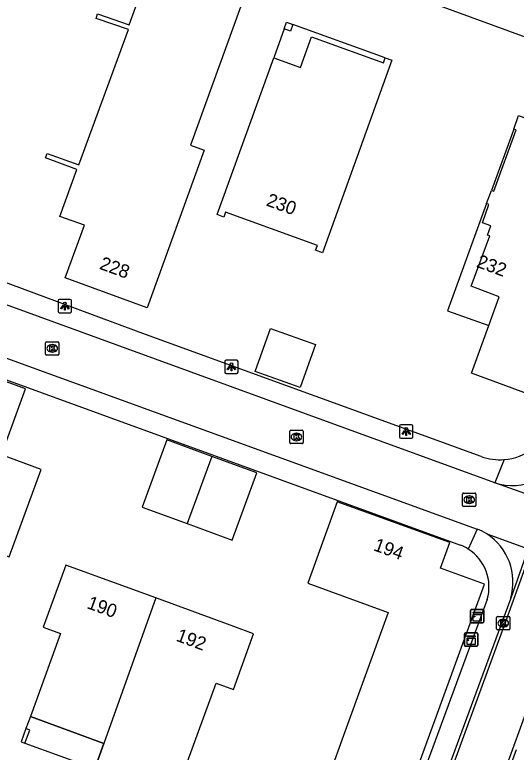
# Model space of a CAD drawing. Extents: x 155275 to 156263, y 382654 to 383635.
# Drawn here: x 155952.1 to 155989.7, y 382926.2 to 382981.5 of the extents above; entities that cross this region are included whole.
import ezdxf

# ---------------------------------------------------------------- set-up
doc = ezdxf.new("R2010")
doc.units = 0
for name, color, linetype in [('IMGEO_Kast', 7, 'Continuous'), ('IMGEO_Kolk', 7, 'Continuous'), ('IMGEO_Lichtpunt', 7, 'Continuous'), ('IMGEO_Pand', 7, 'Continuous'), ('IMGEO_Pand_nummerreeks', 7, 'Continuous'), ('IMGEO_Pand_overbouw', 7, 'Continuous'), ('IMGEO_Rijbaan_lokaal_gesloten', 7, 'Continuous'), ('IMGEO_Rijbaan_lokaal_open', 7, 'Continuous'), ('IMGEO_Voetpad_open', 7, 'Continuous')]:
    doc.layers.add(name, color=color, linetype=linetype)

msp = doc.modelspace()

# ---------------------------------------------------------------- linework, layer by layer
at = {"layer": 'IMGEO_Kast'}
for p, q in [((155986.365, 382936.948), (155987.206, 382936.948)), ((155987.206, 382936.948), (155986.365, 382936.948)), ((155986.29, 382936.023), (155986.29, 382936.864)), ((155986.29, 382936.864), (155986.29, 382936.023)), ((155987.29, 382936.873), (155987.29, 382936.032)), ((155987.29, 382936.032), (155987.29, 382936.873)), ((155987.215, 382935.948), (155986.374, 382935.948)), ((155986.374, 382935.948), (155987.215, 382935.948)), ((155985.83, 382934.257), (155985.83, 382935.098)), ((155985.83, 382935.098), (155985.83, 382934.257)), ((155985.905, 382935.182), (155986.746, 382935.182)), ((155986.746, 382935.182), (155985.905, 382935.182)), ((155986.83, 382935.107), (155986.83, 382934.266)), ((155986.83, 382934.266), (155986.83, 382935.107)), ((155986.755, 382934.182), (155985.914, 382934.182)), ((155985.914, 382934.182), (155986.755, 382934.182))]:
    msp.add_line(p, q, dxfattribs=at)
for points in [[(155986.485, 382936.738), (155987.085, 382936.738), (155987.085, 382936.653), (155986.485, 382936.653), (155986.485, 382936.738)], [(155986.485, 382936.563), (155987.085, 382936.563), (155987.085, 382936.074), (155986.485, 382936.074), (155986.485, 382936.563)], [(155986.025, 382934.972), (155986.625, 382934.972), (155986.625, 382934.887), (155986.025, 382934.887), (155986.025, 382934.972)], [(155986.025, 382934.797), (155986.625, 382934.797), (155986.625, 382934.308), (155986.025, 382934.308), (155986.025, 382934.797)]]:
    msp.add_lwpolyline(points, dxfattribs=at)
for centre in [(155986.569, 382936.412), (155986.109, 382934.646)]:
    msp.add_circle(centre, 0.0377, dxfattribs=at)
for centre, start, end in [((155986.368, 382936.87), 92.4484, 184.2845), ((155986.368, 382936.87), 92.4484, 184.2845), ((155987.212, 382936.87), 2.4484, 94.2845), ((155987.212, 382936.87), 2.4484, 94.2845), ((155986.368, 382936.026), 182.4484, 274.2845), ((155986.368, 382936.026), 182.4484, 274.2845), ((155987.212, 382936.026), 272.4484, 4.2845), ((155987.212, 382936.026), 272.4484, 4.2845), ((155985.908, 382935.104), 92.4484, 184.2845), ((155985.908, 382935.104), 92.4484, 184.2845), ((155986.752, 382935.104), 2.4484, 94.2845), ((155986.752, 382935.104), 2.4484, 94.2845), ((155985.908, 382934.26), 182.4484, 274.2845), ((155985.908, 382934.26), 182.4484, 274.2845), ((155986.752, 382934.26), 272.4484, 4.2845), ((155986.752, 382934.26), 272.4484, 4.2845)]:
    msp.add_arc(centre, 0.0779, start, end, dxfattribs=at)
at = {"layer": 'IMGEO_Kolk'}
for p, q in [((155954.389, 382956.097), (155954.389, 382956.949)), ((155954.464, 382957.023), (155955.316, 382957.023)), ((155954.877, 382956.803), (155954.902, 382956.803)), ((155955.39, 382956.949), (155955.39, 382956.097)), ((155954.9, 382956.243), (155954.875, 382956.243)), ((155955.316, 382956.023), (155954.464, 382956.023)), ((155972.719, 382949.453), (155972.719, 382950.305)), ((155972.794, 382950.379), (155973.646, 382950.379)), ((155973.207, 382950.159), (155973.232, 382950.159)), ((155973.72, 382950.305), (155973.72, 382949.453)), ((155973.646, 382949.379), (155972.794, 382949.379)), ((155973.23, 382949.599), (155973.205, 382949.599)), ((155985.689, 382944.749), (155985.689, 382945.601)), ((155985.764, 382945.675), (155986.616, 382945.675)), ((155986.177, 382945.455), (155986.202, 382945.455)), ((155986.69, 382945.601), (155986.69, 382944.749)), ((155986.616, 382944.675), (155985.764, 382944.675)), ((155986.2, 382944.895), (155986.175, 382944.895)), ((155988.245, 382935.49), (155988.245, 382936.342)), ((155988.32, 382936.416), (155989.172, 382936.416)), ((155989.246, 382936.342), (155989.246, 382935.49)), ((155988.733, 382936.196), (155988.758, 382936.196)), ((155989.172, 382935.416), (155988.32, 382935.416)), ((155988.756, 382935.636), (155988.731, 382935.636))]:
    msp.add_line(p, q, dxfattribs=at)
for points in [[(155954.389, 382956.097), (155954.389, 382956.949)], [(155954.464, 382957.023), (155955.316, 382957.023)], [(155955.39, 382956.949), (155955.39, 382956.097)], [(155954.71, 382956.723), (155954.833, 382956.723), (155954.833, 382956.572), (155954.963, 382956.723), (155955.127, 382956.723), (155954.981, 382956.572), (155955.134, 382956.323), (155954.982, 382956.323), (155954.897, 382956.487), (155954.833, 382956.42), (155954.833, 382956.323), (155954.71, 382956.323), (155954.71, 382956.723)], [(155955.316, 382956.023), (155954.464, 382956.023)], [(155972.719, 382949.453), (155972.719, 382950.305)], [(155972.794, 382950.379), (155973.646, 382950.379)], [(155973.72, 382950.305), (155973.72, 382949.453)], [(155973.04, 382950.079), (155973.163, 382950.079), (155973.163, 382949.928), (155973.293, 382950.079), (155973.457, 382950.079), (155973.311, 382949.928), (155973.464, 382949.679), (155973.312, 382949.679), (155973.227, 382949.843), (155973.163, 382949.776), (155973.163, 382949.679), (155973.04, 382949.679), (155973.04, 382950.079)], [(155973.646, 382949.379), (155972.794, 382949.379)], [(155985.689, 382944.749), (155985.689, 382945.601)], [(155985.764, 382945.675), (155986.616, 382945.675)], [(155986.01, 382945.375), (155986.133, 382945.375), (155986.133, 382945.224), (155986.263, 382945.375), (155986.427, 382945.375), (155986.281, 382945.224), (155986.434, 382944.975), (155986.282, 382944.975), (155986.197, 382945.139), (155986.133, 382945.072), (155986.133, 382944.975), (155986.01, 382944.975), (155986.01, 382945.375)], [(155986.69, 382945.601), (155986.69, 382944.749)], [(155986.616, 382944.675), (155985.764, 382944.675)], [(155988.245, 382935.49), (155988.245, 382936.342)], [(155988.32, 382936.416), (155989.172, 382936.416)], [(155989.246, 382936.342), (155989.246, 382935.49)], [(155988.566, 382936.116), (155988.689, 382936.116), (155988.689, 382935.965), (155988.819, 382936.116), (155988.983, 382936.116), (155988.837, 382935.965), (155988.99, 382935.716), (155988.838, 382935.716), (155988.753, 382935.88), (155988.689, 382935.813), (155988.689, 382935.716), (155988.566, 382935.716), (155988.566, 382936.116)], [(155989.172, 382935.416), (155988.32, 382935.416)]]:
    msp.add_lwpolyline(points, dxfattribs=at)
for centre, start, end in [((155954.466, 382956.947), 91.552, 178.448), ((155954.466, 382956.947), 91.552, 178.448), ((155955.314, 382956.947), 1.552, 88.448), ((155955.314, 382956.947), 1.552, 88.448), ((155954.466, 382956.099), 181.552, 268.448), ((155954.466, 382956.099), 181.552, 268.448), ((155955.314, 382956.099), 271.552, 358.448), ((155955.314, 382956.099), 271.552, 358.448), ((155972.796, 382950.303), 91.552, 178.448), ((155972.796, 382950.303), 91.552, 178.448), ((155973.644, 382950.303), 1.552, 88.448), ((155973.644, 382950.303), 1.552, 88.448), ((155972.796, 382949.455), 181.552, 268.448), ((155972.796, 382949.455), 181.552, 268.448), ((155973.644, 382949.455), 271.552, 358.448), ((155973.644, 382949.455), 271.552, 358.448), ((155985.766, 382945.599), 91.552, 178.448), ((155985.766, 382945.599), 91.552, 178.448), ((155986.614, 382945.599), 1.552, 88.448), ((155986.614, 382945.599), 1.552, 88.448), ((155985.766, 382944.751), 181.552, 268.448), ((155985.766, 382944.751), 181.552, 268.448), ((155986.614, 382944.751), 271.552, 358.448), ((155986.614, 382944.751), 271.552, 358.448), ((155988.322, 382936.34), 91.552, 178.448), ((155988.322, 382936.34), 91.552, 178.448), ((155989.17, 382936.34), 1.552, 88.448), ((155989.17, 382936.34), 1.552, 88.448), ((155988.322, 382935.492), 181.552, 268.448), ((155988.322, 382935.492), 181.552, 268.448), ((155989.17, 382935.492), 271.552, 358.448), ((155989.17, 382935.492), 271.552, 358.448)]:
    msp.add_arc(centre, 0.0765, start, end, dxfattribs=at)
for centre, major_axis, ratio, start_param, end_param in [((155954.876, 382956.523), (-0.387, 0.002), 0.722429, 4.712389, 7.853982), ((155954.901, 382956.523), (-0.39, 0.002), 0.717154, 1.570796, 4.712389), ((155973.206, 382949.879), (-0.387, 0.002), 0.722429, 4.712389, 7.853982), ((155973.231, 382949.879), (-0.39, 0.002), 0.717154, 1.570796, 4.712389), ((155986.176, 382945.175), (-0.387, 0.002), 0.722429, 4.712389, 7.853982), ((155986.201, 382945.175), (-0.39, 0.002), 0.717154, 1.570796, 4.712389), ((155988.732, 382935.916), (-0.387, 0.002), 0.722429, 4.712389, 7.853982), ((155988.757, 382935.916), (-0.39, 0.002), 0.717154, 1.570796, 4.712389)]:
    msp.add_ellipse(centre, major_axis=major_axis, ratio=ratio, start_param=start_param, end_param=end_param, dxfattribs=at)
at = {"layer": 'IMGEO_Lichtpunt'}
for p, q in [((155956.237, 382960.197), (155955.429, 382960.197)), ((155956.237, 382960.197), (155955.429, 382960.197)), ((155955.335, 382960.102), (155955.335, 382959.295)), ((155955.335, 382960.102), (155955.335, 382959.295)), ((155956.331, 382959.295), (155956.331, 382960.102)), ((155956.331, 382959.295), (155956.331, 382960.102)), ((155955.429, 382959.201), (155956.237, 382959.201)), ((155955.429, 382959.201), (155956.237, 382959.201)), ((155967.835, 382955.546), (155967.835, 382954.739)), ((155967.835, 382955.546), (155967.835, 382954.739)), ((155968.737, 382955.641), (155967.929, 382955.641)), ((155968.737, 382955.641), (155967.929, 382955.641)), ((155968.831, 382954.739), (155968.831, 382955.546)), ((155968.831, 382954.739), (155968.831, 382955.546)), ((155967.929, 382954.645), (155968.737, 382954.645)), ((155967.929, 382954.645), (155968.737, 382954.645)), ((155981.859, 382950.793), (155981.051, 382950.793)), ((155981.859, 382950.793), (155981.051, 382950.793)), ((155980.957, 382950.698), (155980.957, 382949.891)), ((155980.957, 382950.698), (155980.957, 382949.891)), ((155981.953, 382949.891), (155981.953, 382950.698)), ((155981.953, 382949.891), (155981.953, 382950.698)), ((155981.051, 382949.797), (155981.859, 382949.797)), ((155981.051, 382949.797), (155981.859, 382949.797))]:
    msp.add_line(p, q, dxfattribs=at)
for points in [[(155955.709, 382959.766), (155955.748, 382959.738), (155955.56, 382959.476), (155955.522, 382959.503), (155955.709, 382959.766)], [(155955.811, 382959.718), (155955.858, 382959.718), (155955.858, 382959.396), (155955.811, 382959.396), (155955.811, 382959.718)], [(155955.921, 382959.738), (155955.959, 382959.765), (155956.146, 382959.503), (155956.107, 382959.475), (155955.921, 382959.738)], [(155968.209, 382955.21), (155968.248, 382955.182), (155968.06, 382954.92), (155968.022, 382954.947), (155968.209, 382955.21)], [(155968.311, 382955.162), (155968.358, 382955.162), (155968.358, 382954.84), (155968.311, 382954.84), (155968.311, 382955.162)], [(155968.421, 382955.182), (155968.459, 382955.209), (155968.646, 382954.947), (155968.607, 382954.919), (155968.421, 382955.182)], [(155981.331, 382950.362), (155981.37, 382950.334), (155981.182, 382950.072), (155981.144, 382950.099), (155981.331, 382950.362)], [(155981.433, 382950.314), (155981.48, 382950.314), (155981.48, 382949.992), (155981.433, 382949.992), (155981.433, 382950.314)], [(155981.543, 382950.334), (155981.581, 382950.361), (155981.768, 382950.099), (155981.729, 382950.071), (155981.543, 382950.334)]]:
    msp.add_lwpolyline(points, dxfattribs=at)
for centre in [(155955.834, 382959.9), (155968.334, 382955.344), (155981.456, 382950.496)]:
    msp.add_circle(centre, 0.0994, dxfattribs=at)
for centre, start, end in [((155955.429, 382960.102), 90, 180), ((155955.429, 382960.102), 90, 180), ((155956.237, 382960.102), 0, 90), ((155956.237, 382960.102), 0, 90), ((155955.429, 382959.295), 180, 270), ((155955.429, 382959.295), 180, 270), ((155956.237, 382959.295), 270, 0), ((155956.237, 382959.295), 270, 360), ((155967.929, 382955.546), 90, 180), ((155967.929, 382955.546), 90, 180), ((155968.737, 382955.546), 0, 90), ((155968.737, 382955.546), 0, 90), ((155967.929, 382954.739), 180, 270), ((155967.929, 382954.739), 180, 270), ((155968.737, 382954.739), 270, 0), ((155968.737, 382954.739), 270, 360), ((155981.051, 382950.698), 90, 180), ((155981.051, 382950.698), 90, 180), ((155981.859, 382950.698), 0, 90), ((155981.859, 382950.698), 0, 90), ((155981.051, 382949.891), 180, 270), ((155981.051, 382949.891), 180, 270), ((155981.859, 382949.891), 270, 0), ((155981.859, 382949.891), 270, 360)]:
    msp.add_arc(centre, 0.0946, start, end, dxfattribs=at)
at = {"layer": 'IMGEO_Pand'}
for points in [[(155960.621, 382980.451), (155958.174, 382981.265), (155958.291, 382981.603), (155960.663, 382980.8), (155962.083, 382984.709), (155969.038, 382982.182), (155965.254, 382971.768), (155966.297, 382971.389), (155962.012, 382959.573), (155955.852, 382961.824), (155957.301, 382965.753), (155955.461, 382966.423), (155956.725, 382969.934), (155954.371, 382970.808), (155954.492, 382971.137), (155956.893, 382970.28), (155960.621, 382980.451)], [(155972.471, 382980.985), (155972.954, 382980.819), (155972.782, 382980.319), (155972.299, 382980.485), (155972.471, 382980.985)], [(155971.515, 382978.319), (155973.518, 382977.594), (155974.35, 382979.892), (155979.742, 382977.94), (155979.879, 382978.316), (155980.386, 382978.133), (155975.162, 382963.699), (155974.658, 382963.878), (155974.789, 382964.246), (155967.898, 382966.736), (155967.763, 382966.37), (155967.256, 382966.557), (155971.515, 382978.319)], [(155987.667, 382967.311), (155987.492, 382967.391), (155987.852, 382968.375), (155988.03, 382968.31), (155989.708, 382972.908), (155989.53, 382972.973), (155989.896, 382973.978), (155994.03, 382972.473), (155994.256, 382973.093), (155998.795, 382971.44), (155996.2, 382964.324), (155994.04, 382965.074), (155993.458, 382963.467), (155994.256, 382963.174), (155990.565, 382953.118), (155986.347, 382954.665), (155987.649, 382958.238), (155988.434, 382960.396), (155986.331, 382961.177), (155987.735, 382964.959), (155987.556, 382965.026), (155987.806, 382965.713), (155987.178, 382965.937), (155987.667, 382967.311)], [(155971.271, 382958.011), (155974.652, 382956.803), (155973.503, 382953.588), (155970.122, 382954.796), (155971.271, 382958.011)], [(155941.404, 382931.098), (155948.452, 382928.54), (155948.578, 382928.877), (155951.055, 382935.678), (155947.309, 382937.08), (155949.099, 382941.866), (155951.656, 382940.886), (155954.05, 382947.443), (155951.075, 382948.529), (155952.877, 382953.502), (155949.924, 382954.572)], [(155966.864, 382948.424), (155963.482, 382949.653), (155961.628, 382944.627), (155965.009, 382943.383)], [(155966.864, 382948.424), (155965.009, 382943.383)], [(155965.009, 382943.383), (155968.391, 382942.139), (155970.239, 382947.198), (155966.864, 382948.424)], [(155984.722, 382941.957), (155976.274, 382945.018), (155974.071, 382938.922), (155980.105, 382936.721), (155976.657, 382927.206), (155974.99, 382922.606), (155980.088, 382920.758), (155979.359, 382918.75), (155978.888, 382918.921), (155978.654, 382918.298), (155979.709, 382917.923), (155987.327, 382938.836), (155984.03, 382940.041), (155984.722, 382941.957)], [(155962.652, 382937.803), (155955.904, 382940.27), (155954.204, 382935.624), (155955.51, 382935.149), (155953.241, 382928.908), (155958.756, 382926.902)], [(155958.756, 382926.902), (155958.083, 382925.019), (155964.053, 382922.854), (155967.185, 382931.416), (155968.482, 382930.944), (155970.001, 382935.116), (155968.528, 382935.654), (155962.652, 382937.803)], [(155962.652, 382937.803), (155958.756, 382926.902)], [(155953.193, 382927.902), (155952.911, 382928.005), (155952.551, 382927.025), (155952.835, 382926.926), (155953.193, 382927.902)]]:
    msp.add_lwpolyline(points, dxfattribs=at)
at = {"layer": 'IMGEO_Pand_overbouw'}
for points in [[(155972.299, 382980.485), (155971.515, 382978.319), (155973.518, 382977.594), (155974.35, 382979.892), (155979.742, 382977.94), (155979.879, 382978.316), (155972.954, 382980.819), (155972.782, 382980.319)], [(155987.852, 382968.375), (155988.03, 382968.31), (155989.708, 382972.908), (155989.53, 382972.973)], [(155987.649, 382958.238), (155988.434, 382960.396), (155986.331, 382961.177), (155987.735, 382964.959), (155987.556, 382965.026), (155987.806, 382965.713), (155987.178, 382965.937), (155987.667, 382967.311), (155987.492, 382967.391), (155984.554, 382959.342)], [(155958.083, 382925.019), (155958.756, 382926.902), (155953.241, 382928.908), (155952.911, 382928.005), (155952.551, 382927.025), (155952.835, 382926.926)]]:
    msp.add_lwpolyline(points, close=True, dxfattribs=at)
at = {"layer": 'IMGEO_Rijbaan_lokaal_gesloten'}
for points in [[(155967.181, 382876.387), (155968.713, 382880.618), (155976.296, 382901.446), (155981.859, 382916.715), (155988.961, 382936.106), (155990.869, 382941.386)], [(155990.616, 382941.478), (155989.298, 382937.8)], [(155994.401, 382940.096), (155992.82, 382935.75), (155984.021, 382911.618), (155973.447, 382882.532), (155970.743, 382875.09)], [(155989.298, 382937.8), (155988.716, 382936.177), (155981.583, 382916.812), (155976.023, 382901.548), (155968.442, 382880.729), (155968.205, 382880.073)], [(155988.253, 382922.386), (155989.727, 382926.433)]]:
    msp.add_lwpolyline(points, dxfattribs=at)
at = {"layer": 'IMGEO_Rijbaan_lokaal_open'}
for points in [[(155988.117, 382946.446), (155905.751, 382976.414)], [(155904.203, 382972.936), (155904.459, 382972.843), (155986.792, 382942.972)], [(155991.912, 382945.095), (155988.117, 382946.446)], [(155986.792, 382942.972), (155986.797, 382942.97)], [(155987.503, 382942.616), (155990.616, 382941.478)]]:
    msp.add_lwpolyline(points, dxfattribs=at)
for centre, radius, start, end in [((155989.412, 382950.372), 4.134, 251.7473, 339.3318), ((155985.337, 382939.177), 4.064, 57.794, 68.9461), ((155985.184, 382939.009), 4.288, 343.6179, 57.2646)]:
    msp.add_arc(centre, radius, start, end, dxfattribs=at)
at = {"layer": 'IMGEO_Voetpad_open'}
for points in [[(155914.334, 383007.511), (155930.357, 383001.752), (155939.786, 382998.363), (156001.392, 382975.875)], [(155904.56, 382971.213), (155985.526, 382941.771)], [(155987.088, 382948.412), (155961.887, 382957.565), (155932.61, 382968.402)], [(155988.799, 382948.185), (155988.117, 382946.446)], [(155986.792, 382942.972), (155986.115, 382941.471)], [(155987.536, 382937.682), (155979.368, 382915.548)]]:
    msp.add_lwpolyline(points, dxfattribs=at)
for centre, radius, start, end in [((155988.479, 382952.316), 4.143, 274.4335, 339.5633), ((155988.474, 382952.294), 4.122, 250.3569, 274.5284), ((155984.263, 382938.563), 3.447, 57.5072, 68.5099), ((155984.297, 382938.628), 3.374, 343.7164, 57.399)]:
    msp.add_arc(centre, radius, start, end, dxfattribs=at)

# ---------------------------------------------------------------- texts
at = {"layer": 'IMGEO_Pand_nummerreeks'}
for s, rotation, p in [('230', 340.1331, (155970.884, 382967.252)), ('232', 339.6263, (155986.667, 382962.652)), ('228', 339.9266, (155958.369, 382962.501)), ('194', 340.0812, (155978.94, 382941.393)), ('190', 339.7173, (155957.425, 382937.057)), ('192', 339.7116, (155964.117, 382934.61))]:
    msp.add_text(s, height=1, rotation=rotation, dxfattribs=at).set_placement(p)

doc.saveas('drawing.dxf')
